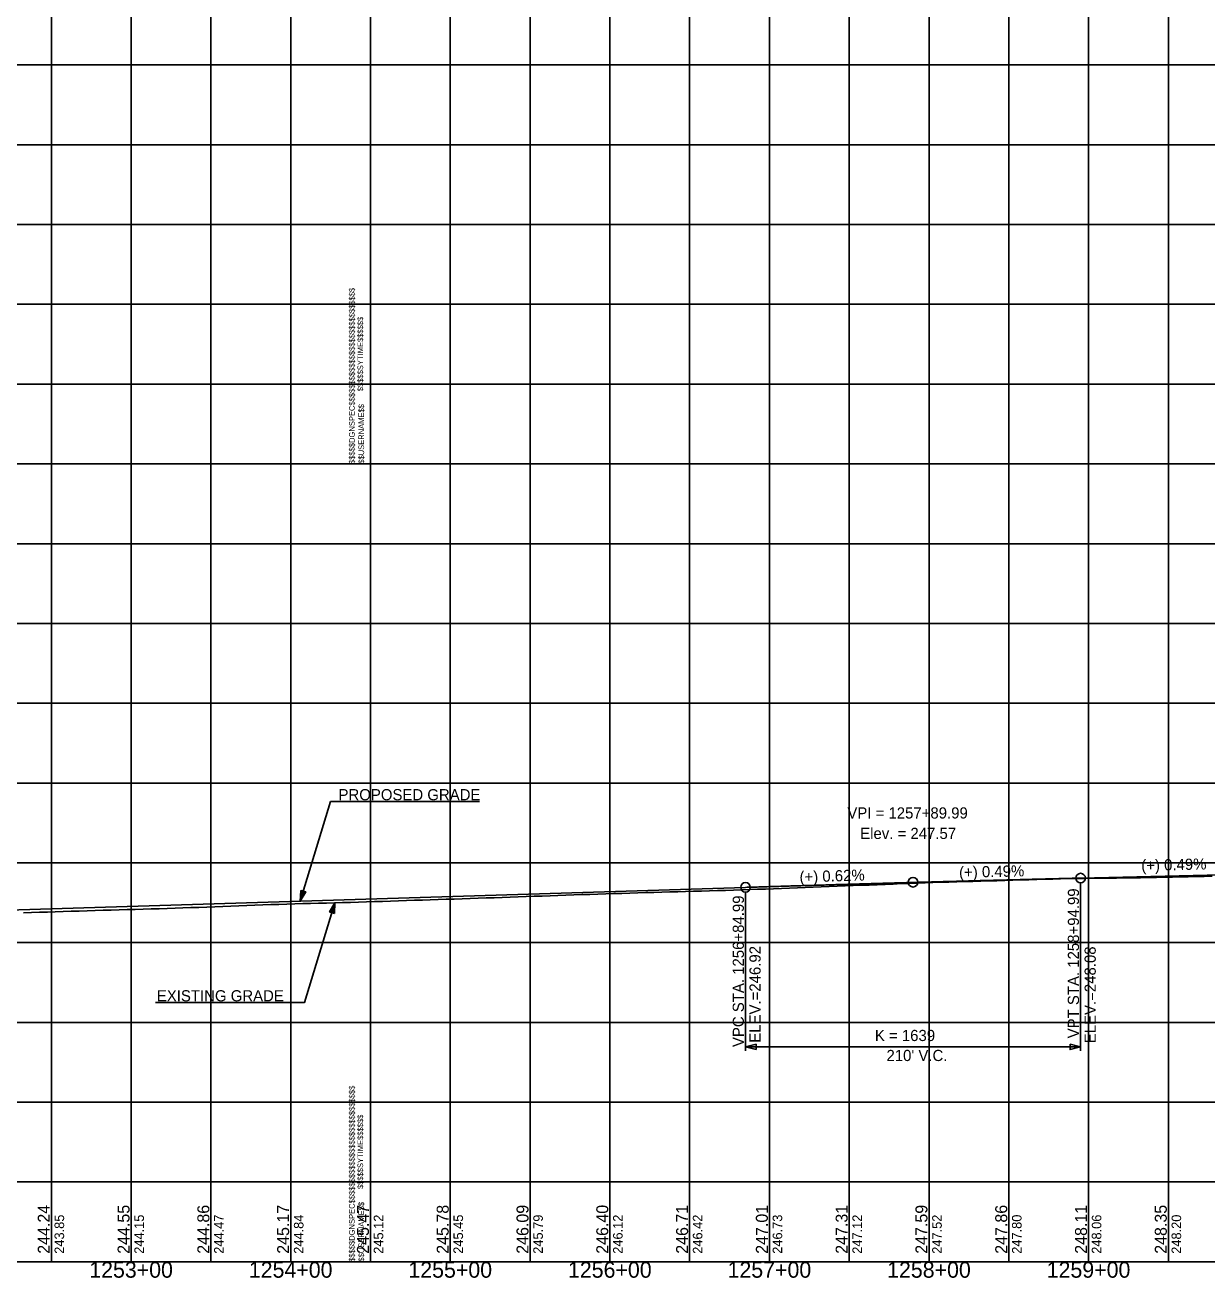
# Model space of a CAD drawing. Extents: x -90830 to 2015517, y -20856 to 836331.
# Drawn here: x 14157 to 14898, y -10807 to -10022 of the extents above; entities that cross this region are included whole.
import ezdxf

# ---------------------------------------------------------------- set-up
doc = ezdxf.new("R2010")
doc.units = 0
for name, color, linetype in [('Level 1', 7, 'Continuous'), ('RD_DDB_GradeTX', 7, 'Continuous'), ('RD_DDB_Profile_Elev', 7, 'Continuous'), ('RD_DDB_Profile_EX', 7, 'Continuous'), ('RD_DDB_Profile_Lbl', 7, 'Continuous'), ('RD_DDB_Profile_PR', 7, 'Continuous'), ('RD_DDB_StaTX', 7, 'Continuous'), ('RD_DDB_StripGrade', 7, 'Continuous'), ('RD_DDB_VCLbl', 7, 'Continuous'), ('RD_GPK_Profile_Cell', 7, 'Continuous'), ('RD_PD_Final_TX', 7, 'Continuous'), ('RD_TX_Drainage', 7, 'Continuous')]:
    doc.layers.add(name, color=color, linetype=linetype)

msp = doc.modelspace()

# ---------------------------------------------------------------- linework, layer by layer
at = {"layer": 'Level 1'}
for p, q in [((14173.46, -9797.12), (14173.46, -10297.12)), ((14223.46, -9797.12), (14223.46, -10297.12)), ((14273.46, -9797.12), (14273.46, -10297.12)), ((14323.46, -9797.12), (14323.46, -10297.12)), ((14373.46, -9797.12), (14373.46, -10297.12)), ((14373.46, -9797.12), (14373.46, -10297.12)), ((14373.46, -9797.12), (14373.46, -10297.12)), ((14423.46, -9797.12), (14423.46, -10297.12)), ((14473.46, -9797.12), (14473.46, -10297.12)), ((14523.46, -9797.12), (14523.46, -10297.12)), ((14573.46, -9797.12), (14573.46, -10297.12)), ((14623.46, -9797.12), (14623.46, -10297.12)), ((14673.46, -9797.12), (14673.46, -10297.12)), ((14723.46, -9797.12), (14723.46, -10297.12)), ((14773.46, -9797.12), (14773.46, -10297.12)), ((14823.46, -9797.12), (14823.46, -10297.12)), ((14873.46, -9797.12), (14873.46, -10297.12)), ((12773.46, -10047.12), (14373.46, -10047.12)), ((14373.46, -10047.12), (15973.46, -10047.12)), ((12773.46, -10097.12), (14373.46, -10097.12)), ((14373.46, -10097.12), (15973.46, -10097.12)), ((12773.46, -10147.12), (14373.46, -10147.12)), ((14373.46, -10147.12), (15973.46, -10147.12)), ((12773.46, -10197.12), (14373.46, -10197.12)), ((14373.46, -10197.12), (15973.46, -10197.12)), ((12773.46, -10247.12), (14373.46, -10247.12)), ((14373.46, -10247.12), (15973.46, -10247.12)), ((12773.46, -10297.12), (14373.46, -10297.12)), ((12773.46, -10297.12), (14373.46, -10297.12)), ((14173.46, -10297.12), (14173.46, -10797.12)), ((14223.46, -10297.12), (14223.46, -10797.12)), ((14273.46, -10297.12), (14273.46, -10797.12)), ((14323.46, -10297.12), (14323.46, -10797.12)), ((14373.46, -10297.12), (14373.46, -10797.12)), ((14373.46, -10297.12), (14373.46, -10797.12)), ((14373.46, -10297.12), (15973.46, -10297.12)), ((14373.46, -10297.12), (15973.46, -10297.12)), ((14373.46, -10297.12), (14373.46, -10797.12)), ((14423.46, -10297.12), (14423.46, -10797.12)), ((14473.46, -10297.12), (14473.46, -10797.12)), ((14523.46, -10297.12), (14523.46, -10797.12)), ((14573.46, -10297.12), (14573.46, -10797.12)), ((14623.46, -10297.12), (14623.46, -10797.12)), ((14673.46, -10297.12), (14673.46, -10797.12)), ((14723.46, -10297.12), (14723.46, -10797.12)), ((14773.46, -10297.12), (14773.46, -10797.12)), ((14823.46, -10297.12), (14823.46, -10797.12)), ((14873.46, -10297.12), (14873.46, -10797.12)), ((12773.46, -10347.12), (14373.46, -10347.12)), ((14373.46, -10347.12), (15973.46, -10347.12)), ((12773.46, -10397.12), (14373.46, -10397.12)), ((14373.46, -10397.12), (15973.46, -10397.12)), ((12773.46, -10447.12), (14373.46, -10447.12)), ((14373.46, -10447.12), (15973.46, -10447.12)), ((12773.46, -10497.12), (14373.46, -10497.12)), ((14373.46, -10497.12), (15973.46, -10497.12)), ((12773.46, -10547.12), (14373.46, -10547.12)), ((14373.46, -10547.12), (15973.46, -10547.12)), ((12773.46, -10597.12), (14373.46, -10597.12)), ((14373.46, -10597.12), (15973.46, -10597.12)), ((12773.46, -10647.12), (14373.46, -10647.12)), ((14373.46, -10647.12), (15973.46, -10647.12)), ((12773.46, -10697.12), (14373.46, -10697.12)), ((14373.46, -10697.12), (15973.46, -10697.12)), ((12773.46, -10747.12), (14373.46, -10747.12)), ((14373.46, -10747.12), (15973.46, -10747.12)), ((12773.46, -10797.12), (14373.46, -10797.12)), ((14373.46, -10797.12), (15973.46, -10797.12))]:
    msp.add_line(p, q, dxfattribs=at)
at = {"layer": 'RD_DDB_GradeTX'}
for p, q in [((14642.48, -10561.46), (14710.45, -10559.36)), ((14784.43, -10557.53), (14716.45, -10559.19))]:
    msp.add_line(p, q, dxfattribs=at)
msp.add_circle((14713.45, -10559.27), 3, dxfattribs=at)
at = {"layer": 'RD_DDB_Profile_EX'}
for points in [[(14545.95, -10565.82), (14550.95, -10565.68), (14555.95, -10565.54), (14560.95, -10565.39), (14565.95, -10565.24), (14570.95, -10565.1), (14575.95, -10564.96), (14580.95, -10564.82), (14585.95, -10564.68), (14590.95, -10564.53), (14595.95, -10564.38), (14600.95, -10564.23), (14605.95, -10564.07), (14610.95, -10563.91), (14615.95, -10563.73), (14620.95, -10563.56), (14625.95, -10563.39), (14630.95, -10563.2), (14635.95, -10563.01), (14640.95, -10562.81), (14645.95, -10562.61), (14650.95, -10562.41), (14655.95, -10562.22), (14660.95, -10562.02), (14665.95, -10561.83), (14670.95, -10561.63), (14675.95, -10561.42), (14680.95, -10561.22), (14685.95, -10561.02), (14690.95, -10560.82), (14695.95, -10560.6), (14700.95, -10560.39), (14705.95, -10560.17), (14710.95, -10559.98), (14715.95, -10559.8), (14720.95, -10559.63), (14725.95, -10559.44), (14730.95, -10559.29), (14735.95, -10559.14), (14740.95, -10559), (14745.95, -10558.86), (14750.95, -10558.73), (14755.95, -10558.59), (14760.95, -10558.46), (14765.95, -10558.33), (14770.95, -10558.18), (14775.95, -10558.03), (14780.95, -10557.88), (14785.95, -10557.74), (14790.95, -10557.58), (14795.95, -10557.43), (14800.95, -10557.28), (14805.95, -10557.13), (14810.95, -10557.03), (14815.95, -10556.94), (14820.95, -10556.85), (14825.95, -10556.77), (14830.95, -10556.73), (14835.95, -10556.69), (14840.95, -10556.66), (14845.95, -10556.62), (14850.95, -10556.53), (14855.95, -10556.43), (14860.95, -10556.33), (14865.95, -10556.23), (14870.95, -10556.15), (14875.95, -10556.07), (14880.95, -10555.99), (14885.95, -10555.9), (14890.95, -10555.78), (14895.95, -10555.66), (14900.95, -10555.54)], [(14155.95, -10578.49), (14160.95, -10578.31), (14165.95, -10578.13), (14170.95, -10577.95), (14175.95, -10577.78), (14180.95, -10577.63), (14185.95, -10577.48), (14190.95, -10577.33), (14195.95, -10577.17), (14200.95, -10577.02), (14205.95, -10576.87), (14210.95, -10576.72), (14215.95, -10576.57), (14220.95, -10576.44), (14225.95, -10576.3), (14230.95, -10576.16), (14235.95, -10576.01), (14240.95, -10575.87), (14245.95, -10575.72), (14250.95, -10575.57), (14255.95, -10575.39), (14260.95, -10575.21), (14265.95, -10575.03), (14270.95, -10574.86), (14275.95, -10574.66), (14280.95, -10574.45), (14285.95, -10574.25), (14290.95, -10574.05), (14295.95, -10573.87), (14300.95, -10573.69), (14305.95, -10573.51), (14310.95, -10573.33), (14315.95, -10573.17), (14320.95, -10573.01), (14325.95, -10572.86), (14330.95, -10572.7), (14335.95, -10572.57), (14340.95, -10572.44), (14345.95, -10572.31), (14350.95, -10572.18), (14355.95, -10572.03), (14360.95, -10571.88), (14365.95, -10571.73), (14370.95, -10571.58), (14375.95, -10571.43), (14380.95, -10571.28), (14385.95, -10571.13), (14390.95, -10570.98), (14395.95, -10570.8), (14400.95, -10570.62), (14405.95, -10570.45), (14410.95, -10570.27), (14415.95, -10570.11), (14420.95, -10569.95), (14425.95, -10569.79), (14430.95, -10569.62), (14435.95, -10569.46), (14440.95, -10569.31), (14445.95, -10569.15), (14450.95, -10568.99), (14455.95, -10568.81), (14460.95, -10568.64), (14465.95, -10568.46), (14470.95, -10568.28), (14475.95, -10568.09), (14480.95, -10567.91), (14485.95, -10567.73), (14490.95, -10567.56), (14495.95, -10567.39), (14500.95, -10567.23), (14505.95, -10567.07), (14510.95, -10566.91), (14515.95, -10566.75), (14520.95, -10566.59), (14525.95, -10566.42), (14530.95, -10566.26), (14535.95, -10566.11), (14540.95, -10565.96), (14545.95, -10565.82)]]:
    msp.add_lwpolyline(points, dxfattribs=at)
at = {"layer": 'RD_DDB_Profile_PR'}
for p, q in [((14818.45, -10556.7), (15018.47, -10551.82)), ((14060.96, -10579.38), (14608.45, -10562.5))]:
    msp.add_line(p, q, dxfattribs=at)
msp.add_spline([(14608.45, -10562.5), (14612.65, -10562.38), (14616.85, -10562.25), (14621.05, -10562.12), (14625.25, -10561.99), (14629.45, -10561.86), (14633.65, -10561.74), (14637.85, -10561.61), (14642.05, -10561.49), (14646.25, -10561.36), (14650.45, -10561.24), (14654.65, -10561.11), (14658.85, -10560.99), (14663.05, -10560.87), (14667.25, -10560.74), (14671.45, -10560.62), (14675.65, -10560.5), (14679.85, -10560.38), (14684.05, -10560.26), (14688.25, -10560.14), (14692.45, -10560.02), (14696.65, -10559.9), (14700.85, -10559.79), (14705.05, -10559.67), (14709.25, -10559.55), (14713.45, -10559.44), (14717.65, -10559.32), (14721.85, -10559.21), (14726.05, -10559.09), (14730.25, -10558.98), (14734.45, -10558.86), (14738.65, -10558.75), (14742.85, -10558.64), (14747.05, -10558.53), (14751.25, -10558.41), (14755.45, -10558.3), (14759.65, -10558.19), (14763.85, -10558.08), (14768.05, -10557.97), (14772.25, -10557.86), (14776.45, -10557.76), (14780.65, -10557.65), (14784.85, -10557.54), (14789.05, -10557.43), (14793.25, -10557.33), (14797.45, -10557.22), (14801.65, -10557.12), (14805.85, -10557.01), (14810.05, -10556.91), (14814.25, -10556.81), (14818.45, -10556.7)], degree=3, dxfattribs=at)
at = {"layer": 'RD_DDB_VCLbl'}
for p, q in [((14818.45, -10665), (14818.45, -10559.7)), ((14608.45, -10665), (14608.45, -10565.5)), ((14608.45, -10662.5), (14818.45, -10662.5))]:
    msp.add_line(p, q, dxfattribs=at)
for centre in [(14608.45, -10562.5), (14818.45, -10556.7)]:
    msp.add_circle(centre, 3, dxfattribs=at)
at = {"layer": 'RD_GPK_Profile_Cell'}
msp.add_line((4823.46, -10797.12), (75223.46, -10797.12), dxfattribs=at)
at = {"layer": 'RD_PD_Final_TX'}
for p, q in [((14329.42, -10571.11), (14329.76, -10564.44)), ((14331.31, -10564.92), (14329.42, -10571.11)), ((14329.42, -10571.11), (14332.86, -10565.39)), ((14329.76, -10564.44), (14332.86, -10565.39)), ((14351.19, -10572.18), (14347.75, -10577.9)), ((14349.3, -10578.37), (14351.19, -10572.18)), ((14351.19, -10572.18), (14350.85, -10578.85)), ((14350.85, -10578.85), (14347.75, -10577.9))]:
    msp.add_line(p, q, dxfattribs=at)
for points in [[(14441.86, -10508.74), (14348.47, -10508.74), (14329.42, -10571.11)], [(14331.24, -10564.98), (14329.48, -10570.75), (14331.21, -10564.93), (14329.51, -10570.46), (14331.14, -10564.94), (14329.51, -10570.27), (14331.06, -10564.92), (14329.51, -10570.03), (14331, -10564.89), (14329.54, -10569.67), (14330.91, -10564.85), (14329.57, -10569.29), (14330.83, -10564.85), (14329.59, -10569), (14330.77, -10564.82), (14329.61, -10568.67), (14330.69, -10564.84), (14329.63, -10568.38), (14330.65, -10564.77), (14329.63, -10568.13), (14330.55, -10564.77), (14329.64, -10567.77), (14330.48, -10564.73), (14329.69, -10567.34), (14330.4, -10564.7), (14329.67, -10567.04), (14330.33, -10564.67), (14329.7, -10566.58), (14330.24, -10564.67), (14329.74, -10566.22), (14330.16, -10564.61), (14329.75, -10565.9), (14330.09, -10564.61), (14329.76, -10565.61), (14330.03, -10564.55), (14329.78, -10565.25), (14329.95, -10564.58), (14329.81, -10564.85), (14329.86, -10564.59)], [(14329.58, -10570.73), (14331.33, -10565.01), (14329.68, -10570.53), (14331.41, -10565.03), (14329.78, -10570.35), (14331.47, -10565.02), (14329.9, -10570.19), (14331.51, -10565.05), (14330.03, -10569.99), (14331.58, -10565.06), (14330.15, -10569.8), (14331.63, -10565.07), (14330.28, -10569.58), (14331.7, -10565.08), (14330.44, -10569.3), (14331.79, -10565.12), (14330.57, -10569.06), (14331.85, -10565.11), (14330.71, -10568.81), (14331.91, -10565.14), (14330.87, -10568.58), (14331.97, -10565.16), (14331.02, -10568.32), (14332.01, -10565.21), (14331.22, -10567.97), (14332.08, -10565.21), (14331.37, -10567.75), (14332.14, -10565.2), (14331.56, -10567.46), (14332.2, -10565.24), (14331.71, -10567.16), (14332.27, -10565.28), (14331.85, -10566.92), (14332.34, -10565.34), (14332.02, -10566.7), (14332.39, -10565.36), (14332.2, -10566.35), (14332.49, -10565.33), (14332.31, -10566.15), (14332.59, -10565.37), (14332.44, -10566.02), (14332.68, -10565.46), (14332.76, -10565.42), (14332.65, -10565.45)], [(14238.75, -10634.55), (14332.14, -10634.55), (14351.19, -10572.18)], [(14351.03, -10572.56), (14349.28, -10578.28), (14350.92, -10572.76), (14349.2, -10578.26), (14350.83, -10572.94), (14349.14, -10578.27), (14350.71, -10573.1), (14349.1, -10578.24), (14350.58, -10573.3), (14349.03, -10578.23), (14350.46, -10573.49), (14348.98, -10578.22), (14350.33, -10573.71), (14348.91, -10578.21), (14350.17, -10573.98), (14348.82, -10578.17), (14350.04, -10574.23), (14348.76, -10578.18), (14349.89, -10574.48), (14348.7, -10578.15), (14349.74, -10574.71), (14348.64, -10578.13), (14349.59, -10574.97), (14348.6, -10578.07), (14349.39, -10575.32), (14348.53, -10578.08), (14349.23, -10575.54), (14348.47, -10578.09), (14349.05, -10575.83), (14348.41, -10578.05), (14348.9, -10576.13), (14348.34, -10578.01), (14348.76, -10576.37), (14348.27, -10577.95), (14348.59, -10576.59), (14348.22, -10577.93), (14348.41, -10576.94), (14348.12, -10577.96), (14348.3, -10577.14), (14348.01, -10577.92), (14348.17, -10577.27), (14347.93, -10577.83), (14347.85, -10577.87), (14347.96, -10577.84)], [(14349.37, -10578.31), (14351.13, -10572.54), (14349.4, -10578.36), (14351.1, -10572.82), (14349.47, -10578.35), (14351.1, -10573.02), (14349.55, -10578.36), (14351.09, -10573.26), (14349.61, -10578.4), (14351.07, -10573.61), (14349.69, -10578.44), (14351.04, -10574), (14349.78, -10578.44), (14351.02, -10574.29), (14349.84, -10578.47), (14351, -10574.62), (14349.91, -10578.45), (14350.98, -10574.91), (14349.96, -10578.52), (14350.98, -10575.16), (14350.06, -10578.52), (14350.96, -10575.52), (14350.13, -10578.56), (14350.92, -10575.95), (14350.21, -10578.59), (14350.94, -10576.25), (14350.28, -10578.62), (14350.91, -10576.71), (14350.37, -10578.62), (14350.87, -10577.07), (14350.45, -10578.68), (14350.85, -10577.39), (14350.52, -10578.68), (14350.85, -10577.68), (14350.58, -10578.74), (14350.82, -10578.04), (14350.66, -10578.71), (14350.8, -10578.44), (14350.75, -10578.7)]]:
    msp.add_lwpolyline(points, dxfattribs=at)
at = {"layer": 'RD_TX_Drainage'}
for points in [[(14615.05, -10664.15), (14608.45, -10662.5), (14615.05, -10660.85)], [(14811.85, -10660.85), (14818.45, -10662.5), (14811.85, -10664.15)]]:
    msp.add_lwpolyline(points, close=True, dxfattribs=at)

# ---------------------------------------------------------------- texts
at = {"layer": 'Level 1'}
for s, p in [('$$$$$DGNSPEC$$$$$$$$$$$$$$$$$$$$$$$$$$$$', (14363.56, -10297.17)), ('$$$$$SYTIME$$$$$$', (14368.86, -10251.57)), ('$$USERNAME$$', (14369.46, -10297.02)), ('$$$$$DGNSPEC$$$$$$$$$$$$$$$$$$$$$$$$$$$$', (14363.56, -10797.17)), ('$$$$$SYTIME$$$$$$', (14368.86, -10751.57)), ('$$USERNAME$$', (14369.46, -10797.02))]:
    msp.add_text(s, height=3.5436, rotation=90, dxfattribs=at).set_placement(p)
at = {"layer": 'RD_DDB_GradeTX'}
for s, rotation, p in [('(+) 0.49%', 1.3989, (14856.56, -10552.25)), ('(+) 0.62%', 1.7657, (14642.42, -10559.46)), ('(+) 0.49%', 1.3989, (14742.39, -10556.56))]:
    msp.add_text(s, height=7, rotation=rotation, dxfattribs=at).set_placement(p)
at = {"layer": 'RD_DDB_Profile_Elev'}
for s, p in [('244.24', (14172.46, -10792.12)), ('244.55', (14222.46, -10792.12)), ('244.86', (14272.46, -10792.12)), ('245.17', (14322.46, -10792.12)), ('245.47', (14372.46, -10792.12)), ('245.78', (14422.46, -10792.12)), ('246.09', (14472.46, -10792.12)), ('246.40', (14522.46, -10792.12)), ('246.71', (14572.46, -10792.12)), ('247.01', (14622.46, -10792.12)), ('247.31', (14672.46, -10792.12)), ('247.59', (14722.46, -10792.12)), ('247.86', (14772.46, -10792.12)), ('248.11', (14822.46, -10792.12)), ('248.35', (14872.46, -10792.12))]:
    msp.add_text(s, height=7.5, rotation=90, dxfattribs=at).set_placement(p)
at = {"layer": 'RD_DDB_Profile_Lbl'}
for s, p in [('VPI = 1257+89.99', (14672.29, -10519.36)), ('Elev. = 247.57', (14680.34, -10532.18))]:
    msp.add_text(s, height=7, dxfattribs=at).set_placement(p)
at = {"layer": 'RD_DDB_StaTX'}
for s, p in [('1253+00', (14197.21, -10807.12)), ('1254+00', (14297.21, -10807.12)), ('1255+00', (14397.21, -10807.12)), ('1256+00', (14497.21, -10807.12)), ('1257+00', (14597.21, -10807.12)), ('1258+00', (14697.21, -10807.12)), ('1259+00', (14797.21, -10807.12))]:
    msp.add_text(s, height=10, dxfattribs=at).set_placement(p)
at = {"layer": 'RD_DDB_StripGrade'}
for s, height, p in [(' VPT STA. 1258+94.99 ', 7, (14817.45, -10659.69)), ('VPC STA. 1256+84.99 ', 7, (14607.45, -10662.57)), ('ELEV.=246.92', 7, (14617.95, -10659.87)), ('ELEV.=248.08', 7, (14827.95, -10660.16)), ('243.85', 6, (14181.46, -10792.12)), ('244.15', 6, (14231.46, -10792.12)), ('244.47', 6, (14281.46, -10792.12)), ('244.84', 6, (14331.46, -10792.12)), ('245.12', 6, (14381.46, -10792.12)), ('245.45', 6, (14431.46, -10792.12)), ('245.79', 6, (14481.46, -10792.12)), ('246.12', 6, (14531.46, -10792.12)), ('246.42', 6, (14581.46, -10792.12)), ('246.73', 6, (14631.46, -10792.12)), ('247.12', 6, (14681.46, -10792.12)), ('247.52', 6, (14731.46, -10792.12)), ('247.80', 6, (14781.46, -10792.12)), ('248.06', 6, (14831.46, -10792.12)), ('248.20', 6, (14881.46, -10792.12))]:
    msp.add_text(s, height=height, rotation=90, dxfattribs=at).set_placement(p)
at = {"layer": 'RD_DDB_VCLbl'}
for s, p in [('K = 1639', (14689.54, -10658.81)), ("210' V.C.", (14696.81, -10671.34))]:
    msp.add_text(s, height=7, dxfattribs=at).set_placement(p)
at = {"layer": 'RD_PD_Final_TX'}
for s, p in [('PROPOSED GRADE', (14353.41, -10507.92)), ('EXISTING GRADE', (14239.57, -10633.94))]:
    msp.add_text(s, height=7, dxfattribs=at).set_placement(p)

doc.saveas('drawing.dxf')
